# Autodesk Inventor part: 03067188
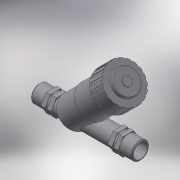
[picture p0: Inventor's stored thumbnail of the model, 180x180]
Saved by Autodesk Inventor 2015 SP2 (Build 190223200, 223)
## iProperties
Created: 2017-05
Part Number: 03067188
Material: Generic
Description: PLASSON CHECK VALVE 1.1/4"
Document SubType Name: Modeling
Designer: KIM
Mass: 228.741 g
Surface Area: 415.565 cm^2
Volume: 228.741 cm^3
Density: 1 g/cm^3
Appearance: Default
Author: KIM
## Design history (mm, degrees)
derived "03067-03068.ipt"
feature "Solid1::03067-03068.ipt"
tag "TaggingFeature1"
body "Solid1"
other parameters: "d0" = 225, "d1" = 47.803, "d3" = 38.2424, "d4" = 22, "d5" = 22, "d6" = 22.5, "d8" = 2.25, "d12" = 0, "d14" = -11.25, "d15" = 4.5, "d16" = 0, "d17" = 58.59, "d18" = 8.37, "d20" = 73.2375, "d21" = 135 deg, "d22" = 76.725, "d23" = 41.85, "d24" = 90.675, "d25" = 20.925, "d29" = 20.925, "d31" = 20.925, "d32" = 69.75, "d34" = 135 deg, "d35" = 2, "d36" = 139.5, "d39" = 78.75, "d40" = 3.1, "d80" = 87.95475, "d81" = 6.2, "d82" = 3.1, "d83" = 36.27, "d84" = 0, "d86" = 360 deg, "d88" = 1.55, "d90" = 1, "d91" = 155, "d92" = 2.0925, "H_" = 225, "R_" = 47.803, "l_2" = 22, "A_" = 155, "d13" = 22.5, "d79" = 90.675
